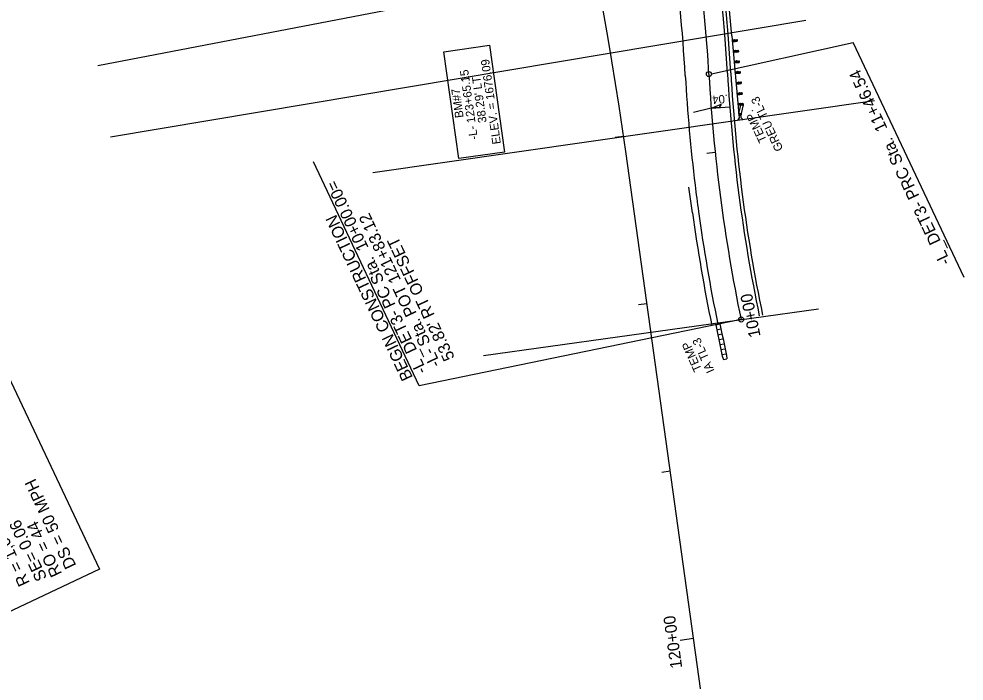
# Model space of a CAD drawing. Extents: x 473658 to 481584, y 489119 to 506230.
# Drawn here: x 477538 to 478097, y 498575 to 498967 of the extents above; entities that cross this region are included whole.
import ezdxf

# ---------------------------------------------------------------- set-up
doc = ezdxf.new("R2010")
doc.units = 0
for name, color, linetype in [('Default', 7, 'Continuous'), ('Exist Structure Minor Culvert Topo', 7, 'Continuous'), ('Exist Structure Minor Pipes RCP 12 Inch Leader', 7, 'Continuous'), ('Prop Conc Barrier', 7, 'Continuous'), ('Prop EOT', 7, 'Continuous'), ('Prop Grid Mask', 7, 'Continuous'), ('Prop Guardrail', 7, 'Continuous'), ('Prop Guardrail Anchor Unit CELL', 7, 'Continuous'), ('Prop Horizontal Alignment', 7, 'Continuous'), ('Prop Horizontal Alignment Curve and Spiral Data', 7, 'Continuous'), ('Prop Horizontal Alignment Station Label', 7, 'Continuous'), ('Prop Horizontal Alignment Tick Label', 7, 'Continuous'), ('Prop Horizontal Alignment Tick Large', 7, 'Continuous'), ('Prop Horizontal Alignment Tick Small', 7, 'Continuous'), ('Prop Paved Shoulder', 7, 'Continuous'), ('Prop Superelevation  Arrow CELL', 7, 'Continuous'), ('Prop Superelevation Label', 7, 'Continuous'), ('Scratch_Level_4', 7, 'Continuous'), ('Scratch_Level_5', 7, 'Continuous'), ('Scratch_Level_9', 7, 'Continuous'), ('Sheet Plan And Profile CELL', 7, 'Continuous')]:
    doc.layers.add(name, color=color, linetype=linetype)

msp = doc.modelspace()

# ---------------------------------------------------------------- linework, layer by layer
at = {"layer": 'Exist Structure Minor Pipes RCP 12 Inch Leader'}
for p, q in [((477950.42, 498785.64), (477952.87, 498786.14)), ((477950.42, 498785.64), (477951.03, 498782.7)), ((477952.87, 498786.14), (477953.48, 498783.21)), ((477951.03, 498782.7), (477953.48, 498783.21)), ((477951.03, 498782.7), (477951.63, 498779.76)), ((477951.63, 498779.76), (477954.08, 498780.27)), ((477951.63, 498779.76), (477952.24, 498776.82)), ((477953.48, 498783.21), (477954.08, 498780.27)), ((477954.08, 498780.27), (477954.69, 498777.33)), ((477952.24, 498776.82), (477954.69, 498777.33)), ((477952.24, 498776.82), (477952.85, 498773.89)), ((477952.85, 498773.89), (477955.29, 498774.39)), ((477952.85, 498773.89), (477953.45, 498770.95)), ((477954.69, 498777.33), (477955.29, 498774.39)), ((477955.29, 498774.39), (477955.9, 498771.45)), ((477953.45, 498770.95), (477955.9, 498771.45)), ((477953.45, 498770.95), (477954.06, 498768.01)), ((477954.06, 498768.01), (477956.51, 498768.52)), ((477954.06, 498768.01), (477954.26, 498767.03)), ((477954.26, 498767.03), (477954.91, 498765.12)), ((477955.9, 498771.45), (477956.51, 498768.52)), ((477956.51, 498768.52), (477956.71, 498767.54)), ((477956.71, 498767.54), (477956.87, 498765.53)), ((477954.91, 498765.12), (477955.89, 498765.32)), ((477955.89, 498765.32), (477956.87, 498765.53))]:
    msp.add_line(p, q, dxfattribs=at)
at = {"layer": 'Prop Conc Barrier'}
for centre, radius, start, end in [((476946.95, 498877.04), 987.01, 3.25612, 12.49584), ((478943.59, 498990.63), 1012.86, 183.25597, 186.93877), ((478943.71, 498990.61), 1012.97, 186.93762, 187.82273), ((478944.74, 498990.75), 1014, 187.82263, 191.65587)]:
    msp.add_arc(centre, radius, start, end, dxfattribs=at)
at = {"layer": 'Prop EOT'}
for centre, radius, start, end in [((476947.96, 498877.15), 1011, 3.2561, 24.00169), ((478944.74, 498990.75), 989, 183.2561, 191.65587)]:
    msp.add_arc(centre, radius, start, end, dxfattribs=at)
at = {"layer": 'Prop Grid Mask'}
for points in [[(477479.37, 498590.75), (477271.19, 499031.28), (477377.66, 499081.6), (477585.84, 498641.07)], [(477798.37, 498884.02), (477789.57, 498947.23), (477816.54, 498950.99), (477825.33, 498887.78)]]:
    msp.add_lwpolyline(points, close=True, dxfattribs=at)
at = {"layer": 'Prop Guardrail'}
msp.add_arc((476947.96, 498877.15), 1015, 4.49325, 24.00169, dxfattribs=at)
at = {"layer": 'Prop Guardrail Anchor Unit CELL'}
for p, q in [((477959.85, 498956.67), (477964, 498910.11)), ((477960.07, 498954.14), (477963.06, 498954.41)), ((477960.07, 498954.14), (477960.16, 498953.14)), ((477961.65, 498953.28), (477960.07, 498954.14)), ((477961.57, 498954.27), (477960.16, 498953.14)), ((477960.16, 498953.14), (477963.15, 498953.41)), ((477960.16, 498953.14), (477961.65, 498953.28)), ((477961.57, 498954.27), (477961.65, 498953.28)), ((477963.15, 498953.41), (477961.57, 498954.27)), ((477961.65, 498953.28), (477963.06, 498954.41)), ((477963.06, 498954.41), (477963.15, 498953.41)), ((477960.63, 498947.86), (477963.67, 498948.13)), ((477960.63, 498947.86), (477962.24, 498947)), ((477962.15, 498948), (477960.72, 498946.87)), ((477960.72, 498946.87), (477963.76, 498947.14)), ((477962.15, 498948), (477962.24, 498947)), ((477963.76, 498947.14), (477962.15, 498948)), ((477962.24, 498947), (477963.67, 498948.13)), ((477963.67, 498948.13), (477963.76, 498947.14)), ((477961.19, 498941.59), (477964.23, 498941.86)), ((477961.19, 498941.59), (477962.8, 498940.73)), ((477962.71, 498941.72), (477961.28, 498940.59)), ((477961.28, 498940.59), (477964.31, 498940.86)), ((477962.71, 498941.72), (477962.8, 498940.73)), ((477964.31, 498940.86), (477962.71, 498941.72)), ((477962.8, 498940.73), (477964.23, 498941.86)), ((477964.23, 498941.86), (477964.31, 498940.86)), ((477961.75, 498935.31), (477964.77, 498935.58)), ((477961.75, 498935.31), (477961.84, 498934.31)), ((477961.75, 498935.31), (477963.35, 498934.45)), ((477963.26, 498935.44), (477961.84, 498934.31)), ((477963.26, 498935.44), (477963.35, 498934.45)), ((477964.86, 498934.58), (477963.26, 498935.44)), ((477963.35, 498934.45), (477964.77, 498935.58)), ((477964.77, 498935.58), (477964.86, 498934.58)), ((477961.84, 498934.31), (477964.86, 498934.58)), ((477962.31, 498929.03), (477965.43, 498929.31)), ((477963.96, 498928.18), (477965.43, 498929.31)), ((477965.43, 498929.31), (477965.52, 498928.32)), ((477962.31, 498929.03), (477963.96, 498928.18)), ((477963.87, 498929.17), (477962.4, 498928.04)), ((477962.4, 498928.04), (477965.52, 498928.32)), ((477963.87, 498929.17), (477963.96, 498928.18)), ((477965.52, 498928.32), (477963.87, 498929.17)), ((477962.87, 498922.76), (477965.86, 498923.02)), ((477962.87, 498922.76), (477964.45, 498921.89)), ((477964.36, 498922.89), (477962.96, 498921.76)), ((477962.96, 498921.76), (477965.94, 498922.03)), ((477964.36, 498922.89), (477964.45, 498921.89)), ((477965.94, 498922.03), (477964.36, 498922.89)), ((477964.45, 498921.89), (477965.86, 498923.02)), ((477965.86, 498923.02), (477965.94, 498922.03)), ((477963.43, 498916.48), (477966.48, 498916.75)), ((477963.43, 498916.48), (477965.04, 498915.62)), ((477964.95, 498916.62), (477963.52, 498915.48)), ((477963.52, 498915.48), (477966.57, 498915.76)), ((477965.04, 498915.62), (477963.95, 498910.6)), ((477964.95, 498916.62), (477965.04, 498915.62)), ((477966.57, 498915.76), (477964.95, 498916.62)), ((477965.04, 498915.62), (477966.48, 498916.75)), ((477966.57, 498915.76), (477965.45, 498910.74)), ((477966.48, 498916.75), (477966.57, 498915.76)), ((477964.22, 498908.04), (477963.44, 498906.8)), ((477963.44, 498906.8), (477966.38, 498907.01)), ((477963.95, 498910.6), (477965.45, 498910.74)), ((477965.53, 498909.74), (477963.95, 498910.6)), ((477964.04, 498909.61), (477965.45, 498910.74)), ((477964.04, 498909.61), (477965.53, 498909.74)), ((477964.68, 498910.12), (477964.07, 498910.08)), ((477964.07, 498910.08), (477964.22, 498908.04)), ((477965.29, 498910.17), (477964.68, 498910.12)), ((477965.44, 498908.13), (477965.29, 498910.17)), ((477966.38, 498907.01), (477965.44, 498908.13)), ((477965.45, 498910.74), (477965.49, 498910.24)), ((477965.45, 498910.74), (477965.53, 498909.74))]:
    msp.add_line(p, q, dxfattribs=at)
at = {"layer": 'Prop Horizontal Alignment'}
msp.add_line((478027.55, 497951.3), (477897.19, 498888.08), dxfattribs=at)
for centre, radius, start, end in [((475792.47, 498595.18), 2125, 7.92268, 31.27221), ((476947.96, 498877.15), 1000, 3.2561, 24.00169), ((478944.74, 498990.75), 1000, 183.2561, 191.65587)]:
    msp.add_arc(centre, radius, start, end, dxfattribs=at)
at = {"layer": 'Prop Horizontal Alignment Station Label'}
for p, q in [((477947.85, 498934.04), (478031.64, 498952.6)), ((478097.31, 498813.63), (478031.64, 498952.6)), ((477774.99, 498749.45), (477712.36, 498881.97)), ((477965.36, 498788.72), (477774.99, 498749.45))]:
    msp.add_line(p, q, dxfattribs=at)
for centre in [(477946.35, 498933.95), (477965.36, 498788.72)]:
    msp.add_circle(centre, 1.5, dxfattribs=at)
at = {"layer": 'Prop Horizontal Alignment Tick Large'}
for p, q in [((477965.36, 498788.72), (477957.52, 498787.1)), ((477937.29, 498599.93), (477929.36, 498598.83))]:
    msp.add_line(p, q, dxfattribs=at)
at = {"layer": 'Prop Horizontal Alignment Tick Small'}
for p, q in [((477895.92, 498897.07), (477890.97, 498896.36)), ((477950.08, 498887.55), (477945.1, 498887.03)), ((477909.72, 498798.02), (477904.77, 498797.33)), ((477923.5, 498698.98), (477918.55, 498698.29))]:
    msp.add_line(p, q, dxfattribs=at)
at = {"layer": 'Prop Paved Shoulder'}
msp.add_line((477936.64, 498851.84), (477934.56, 498867), dxfattribs=at)
for centre, radius, start, end in [((476947.96, 498877.15), 1013, 3.2561, 24.00169), ((478944.74, 498990.75), 987, 183.2561, 191.65587), ((478944.85, 498990.35), 1017.68, 187.82263, 191.63226)]:
    msp.add_arc(centre, radius, start, end, dxfattribs=at)
at = {"layer": 'Prop Superelevation  Arrow CELL'}
msp.add_lwpolyline([(477947.7, 498913.76), (477953.53, 498916.22), (477952.32, 498914.12)], close=True, dxfattribs=at)
at = {"layer": 'Prop Superelevation Label'}
msp.add_line((477947.7, 498913.76), (477958.67, 498914.61), dxfattribs=at)
at = {"layer": 'Scratch_Level_4'}
msp.add_line((477947.7, 498913.76), (477937.3, 498911.14), dxfattribs=at)
at = {"layer": 'Scratch_Level_5'}
for p, q in [((477584.76, 498939.14), (477994.45, 499017.76)), ((477592.36, 498896.88), (478003.78, 498965.84))]:
    msp.add_line(p, q, dxfattribs=at)
at = {"layer": 'Scratch_Level_9'}
msp.add_line((477813, 498767.52), (478011.09, 498795.09), dxfattribs=at)
at = {"layer": 'Sheet Plan And Profile CELL'}
msp.add_line((477747.44, 498875.76), (478044.4, 498918.38), dxfattribs=at)

# ---------------------------------------------------------------- texts
at = {"layer": 'Default'}
for s, p in [('ELEV. = 1676.09', (477823.29, 498892.8)), ('-L- 123+65.15', (477809.69, 498895.48)), ("38.29' LT", (477814.91, 498905.46)), ('BM#7', (477801.27, 498908.37))]:
    msp.add_text(s, height=5, rotation=97.9227, dxfattribs=at).set_placement(p)
at = {"layer": 'Exist Structure Minor Culvert Topo'}
for s, p in [('TEMP', (477942.26, 498759.2)), ('IA TL-3', (477949.8, 498758.37))]:
    msp.add_text(s, height=5, rotation=113.8342, dxfattribs=at).set_placement(p)
at = {"layer": 'Prop Guardrail Anchor Unit CELL'}
for s, p in [('GREU TL-3', (477990.45, 498889.65)), ('TEMP. ', (477980.76, 498894.82))]:
    msp.add_text(s, height=5, rotation=115.2938, dxfattribs=at).set_placement(p)
at = {"layer": 'Prop Horizontal Alignment Curve and Spiral Data'}
for s, p in [('DS = 50 MPH', (477572.23, 498643.17)), ("R = 1,000.00'", (477544.73, 498632.88)), ('SE= 0.06', (477554.99, 498635.88)), ('RO = 44', (477563.84, 498638.38))]:
    msp.add_text(s, height=7, rotation=115.2938, dxfattribs=at).set_placement(p)
at = {"layer": 'Prop Horizontal Alignment Station Label'}
for s, p in [('-L_DET3- PRC Sta.  11+46.54', (478089.47, 498822.78)), ('-L_DET3- PC Sta.  10+00.00=', (477779.63, 498758.39)), ('-L- Sta. POT 121+83.12', (477787.89, 498762.29)), ('BEGIN CONSTRUCTION', (477771.38, 498754.49)), ("53.82' RT OFFSET", (477796.15, 498766.2))]:
    msp.add_text(s, height=7, rotation=115.2938, dxfattribs=at).set_placement(p)
at = {"layer": 'Prop Horizontal Alignment Tick Label'}
for s, rotation, p in [('10+00', 101.6559, (477976.99, 498778.88)), ('120+00', 97.9227, (477930.6, 498582.7))]:
    msp.add_text(s, height=7, rotation=rotation, dxfattribs=at).set_placement(p)
at = {"layer": 'Prop Superelevation  Arrow CELL'}
msp.add_text('.04', height=5, rotation=184.3954, dxfattribs=at).set_placement((477957.44, 498921.87))

doc.saveas('drawing.dxf')
